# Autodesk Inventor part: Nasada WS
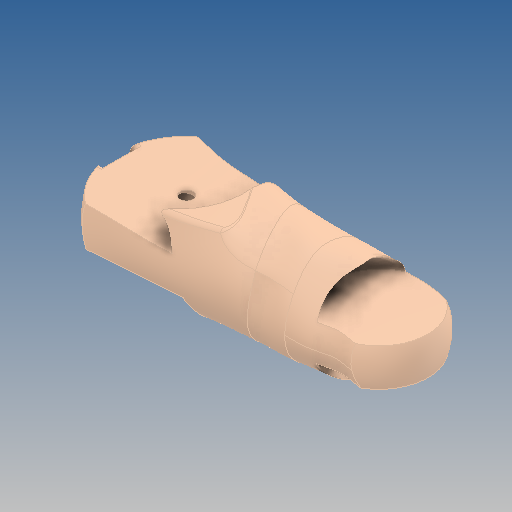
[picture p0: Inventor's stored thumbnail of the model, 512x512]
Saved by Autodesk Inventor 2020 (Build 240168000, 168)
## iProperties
Created: 2019-10
Part Number: Nasada WS
Material: GFRP
Document SubType Name: Modeling
Designer: yello
Density: 1.75 g/cm^3
Appearance: Default
Author: yello
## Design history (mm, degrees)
feature "Nasada WS"
workplane "Work Plane1"
sketch "Sketch2"
  geometry: L1 (3.5, 0)-(3.5, 20); L2 (3.5, 20)-(-3.5, 20); L3 (-3.5, 20)-(-3.5, 0); L4 (-3.5, 0)-(-3.5, -30); L5 (-3.5, -30)-(3.5, -30); L6 (3.5, -30)-(3.5, 0); L7 (0, -30)-(0, 20); A1 r 3.5 centre (0, 0) between (3.5, 0) and (-3.5, 0)
  constraints: 14 end point, 3 perpendicular, 2 midpoint, 2 point on circle, 2 point on line, 2 tangent, 1 centre point, 1 vertical
  dimensions: "d2" = 7 diameter of A1; "d3" = 20 distance of L1.start L1.end; "d4" = 30 distance of L3.end L4.end
revolve "Revolution1" sketch "Sketch2" stored, may be unused: angle "d5" = 90 deg
workplane "Work Plane3"
sketch "Sketch10"
  geometry: C1 r 95.129 at (-22.981, -21.642); 1 further point
  constraints: 1 centre point
workplane "Work Plane5"
sketch "Sketch14"
  geometry: C1 r 4.25 at (0, 0); A1 r 3.5 centre (0, 0) between (3.274, -1.237) and (3.274, -1.237) reference
  constraints: 1 centre point, 1 coincident
  dimensions: "d16" = 8.5 diameter of C1
extrude "Extrusion4" cut sketch "Sketch14" stored distance "d17" = 2; taper "d18" = 0 deg
workplane "Work Plane6"
sketch "Sketch15"
  geometry: L1 (0, 1.5)-(0, -1.5); A1 r 1.5 centre (0, 0) between (0, 1.5) and (0, -1.5); 1 further point
  constraints: 2 end point, 2 point on circle, 1 centre point, 1 vertical
  dimensions: "d21" = 3 diameter of A1
revolve "Revolution2" sketch "Sketch15" stored, may be unused: angle "d22" = 90 deg
mirror "Mirror1"
workaxis "Work Axis1"
fillet "Fillet1" dims "d23" = 1
workplane "Work Plane8"
sketch "Sketch17"
  geometry: L1 (0, 0)-(7, 0) reference; L2 (3.5, 0)-(3.5, 3.75) reference; L3 (3.5, 3.75)-(3.5, 12); L4 (2.5, 3.75)-(2.5, 12); L5 (4.5, 12)-(4.5, 3.75); A1 r 1 centre (3.5, 3.75) between (2.5, 3.75) and (4.5, 3.75); A2 r 1 centre (3.5, 12) between (4.5, 12) and (2.5, 12); 1 further point
  constraints: 12 end point, 4 point on circle, 3 vertical, 2 centre point, 2 midpoint, 1 coincident, 1 equal radius, 1 horizontal, 1 other
  dimensions: "d28" = 8.25 distance of L3.start L3.end; "d31" = 1 radius of A2 (derived); "d34" = 1 radius of A1
extrude "Extrusion5" cut sketch "Sketch17" distance "d29" = 15; taper "d30" = 0 deg
body "Solid1"
other parameters: "d15" = 45, "d19" = 3.5, "d25" = -15
